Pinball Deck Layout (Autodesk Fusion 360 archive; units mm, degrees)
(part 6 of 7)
sketch "Solenoid Coupling" plane through (0, 0, -32.2) normal (0, 0, 1) x axis (1, 0, 0)
  line L1 (14.8548, -15.2705) -> (9.7533, -24.1063)
  line L2 (30.5284, -24.3335) -> (14.8548, -15.2705)
  line L3 (25.433, -33.159) -> (30.5284, -24.3335)
  line L4 (25.433, -33.159) -> (9.7533, -24.1063)
  line L5 (47.3229, -34.0286) -> (34.864, -26.8366)
  line L6 (30.5284, -24.3335) -> (34.864, -26.8366)
  line L7 (34.864, -26.8366) -> (30.629, -34.173)
  line L8 (13.6506, -26.3564) -> (16.6506, -21.1603)
  line L9 (22.6506, -21.1603) -> (16.6506, -21.1603)
  line L10 (13.6506, -26.3564) -> (16.6506, -21.1603)
  line L11 (51.0602, -47.9614) -> (53.55, -46.5429)
  line L12 (51.0602, -47.9614) -> (42.896, -43.2346)
  line L13 (-25.136, -26.8366) -> (-29.3244, -34.0923)
  line L14 (-45.1452, -15.2705) -> (-50.2467, -24.1063)
  line L15 (-34.567, -33.159) -> (-29.4716, -24.3335)
  line L16 (-46.3494, -26.3564) -> (-43.3494, -21.1603)
  line L17 (-8.2143, -48.5931) -> (-5.4963, -46.9921)
  line L18 (-11.811, -34.5286) -> (-25.136, -26.8366)
  line L19 (-29.4716, -24.3335) -> (-25.136, -26.8366)
  line L20 (-29.4716, -24.3335) -> (-45.1452, -15.2705)
  line L21 (-37.3494, -21.1603) -> (-43.3494, -21.1603)
  line L22 (-46.3494, -26.3564) -> (-43.3494, -21.1603)
  line L23 (-10.945, -35.0285) -> (-11.811, -34.5286)
  line L24 (-15.3719, -42.1478) -> (-16.2379, -41.6478)
  line L25 (-89.4716, -24.3335) -> (-105.1452, -15.2705)
  line L26 (-97.3494, -21.1603) -> (-103.3494, -21.1603)
  line L27 (-67.4648, -48.7967) -> (-64.8096, -47.2494)
  line L28 (-106.3494, -26.3564) -> (-103.3494, -21.1603)
  line L29 (-106.3494, -26.3564) -> (-103.3494, -21.1603)
  line L30 (-69.7504, -35.7181) -> (-70.6165, -35.2181)
  line L31 (-70.6165, -35.2181) -> (-85.136, -26.8366)
  line L32 (-74.5059, -42.6477) -> (-75.3719, -42.1477)
  line L33 (-85.136, -26.8366) -> (-89.3244, -34.0922)
  line L34 (-67.4648, -48.7967) -> (-75.3719, -44.2345)
  line L35 (-89.4716, -24.3335) -> (-85.136, -26.8366)
  line L36 (-94.567, -33.159) -> (-89.4716, -24.3335)
  line L37 (-105.1452, -15.2705) -> (-110.2467, -24.1063)
  line L38 (-94.567, -33.159) -> (-110.2467, -24.1063)
  line L39 (-156.3494, -26.3564) -> (-153.3494, -21.1603)
  line L40 (-155.1452, -15.2705) -> (-160.2467, -24.1063)
  line L41 (-147.3494, -21.1603) -> (-153.3494, -21.1603)
  line L42 (-119.2129, -36.0285) -> (-120.0789, -35.5285)
  line L43 (-116.307, -49.4732) -> (-113.7939, -48.0094)
  line L44 (-156.3494, -26.3564) -> (-153.3494, -21.1603)
  line L45 (-144.567, -33.159) -> (-139.4716, -24.3335)
  line L46 (-134.27, -27.3366) -> (-138.4584, -34.5922)
  line L47 (-144.567, -33.159) -> (-160.2467, -24.1063)
  line L48 (-139.4716, -24.3335) -> (-134.27, -27.3366)
  line L49 (-139.4716, -24.3335) -> (-155.1452, -15.2705)
  line L50 (-120.0789, -35.5285) -> (-134.27, -27.3366)
  line L51 (-123.6398, -43.1477) -> (-124.5059, -42.6477)
  line L52 (-116.307, -49.4732) -> (-124.5058, -44.7345)
  line L53 (-204.567, -33.159) -> (-220.2467, -24.1063)
  line L54 (-182.7738, -43.6477) -> (-183.6398, -43.1477)
  line L55 (-207.3494, -21.1603) -> (-213.3494, -21.1603)
  line L56 (-215.1452, -15.2705) -> (-220.2467, -24.1063)
  line L57 (-216.3494, -26.3564) -> (-213.3494, -21.1603)
  line L58 (-216.3494, -26.3564) -> (-213.3494, -21.1603)
  line L59 (-199.4716, -24.3335) -> (-215.1452, -15.2705)
  line L60 (-199.4716, -24.3335) -> (-193.404, -27.8366)
  line L61 (-178.3469, -36.5285) -> (-179.2129, -36.0285)
  line L62 (-179.2129, -36.0285) -> (-193.404, -27.8366)
  line L63 (-175.4401, -49.9688) -> (-183.6398, -45.2345)
  line L64 (-204.567, -33.159) -> (-199.4716, -24.3335)
  line L65 (-175.4401, -49.9688) -> (-172.9348, -48.5134)
  line L66 (-193.404, -27.8366) -> (-197.5924, -35.0922)
  line L67 (-264.567, -33.159) -> (-280.2467, -24.1063)
  line L68 (-275.1452, -15.2705) -> (-280.2467, -24.1063)
  line L69 (-234.5746, -50.467) -> (-232.0726, -49.0156)
  line L70 (-238.3469, -36.5285) -> (-252.538, -28.3366)
  line L71 (-259.4716, -24.3335) -> (-252.538, -28.3366)
  line L72 (-252.538, -28.3366) -> (-256.7263, -35.5922)
  line L73 (-234.5746, -50.467) -> (-242.7738, -45.7345)
  line L74 (-259.4716, -24.3335) -> (-275.1452, -15.2705)
  line L75 (-267.3494, -21.1603) -> (-273.3494, -21.1603)
  line L76 (-276.3494, -26.3564) -> (-273.3494, -21.1603)
  line L77 (-276.3494, -26.3564) -> (-273.3494, -21.1603)
  line L78 (-264.567, -33.159) -> (-259.4716, -24.3335)
  line L79 (25.433, -33.159) -> (42.896, -43.2346)
  line L80 (30.629, -34.173) -> (29.7699, -35.6612)
  line L81 (-30.2298, -35.6615) -> (-29.3244, -34.0923)
  line L82 (-90.23, -35.6618) -> (-75.3719, -44.2345)
  line L83 (-90.23, -35.6618) -> (-89.3244, -34.0922)
  line L84 (-90.23, -35.6618) -> (-94.567, -33.159)
  line L85 (-144.567, -33.159) -> (-124.5058, -44.7345)
  line L86 (-139.3638, -36.1613) -> (-138.4584, -34.5922)
  line L87 (-204.567, -33.159) -> (-183.6398, -45.2345)
  line L88 (-198.4977, -36.6611) -> (-197.5924, -35.0922)
  line L89 (-264.567, -33.159) -> (-242.7738, -45.7345)
  line L90 (-257.6316, -37.161) -> (-256.7263, -35.5922)
  line L91 (-326.2039, -23.3339) -> (-319.2703, -27.337)
  line L92 (-331.2993, -32.1594) -> (-346.979, -23.1067)
  line L93 (-343.0816, -25.3568) -> (-340.0816, -20.1607)
  line L94 (-299.5746, -50.467) -> (-297.0726, -49.0156)
  line L95 (-343.0816, -25.3568) -> (-340.0816, -20.1607)
  line L96 (-334.0816, -20.1607) -> (-340.0816, -20.1607)
  line L97 (-326.2039, -23.3339) -> (-341.8775, -14.2709)
  line L98 (-303.3473, -36.5287) -> (-319.2703, -27.337)
  line L99 (-331.2993, -32.1594) -> (-326.2039, -23.3339)
  line L100 (-319.2703, -27.337) -> (-323.4586, -34.5926)
  line L101 (-299.5746, -50.467) -> (-307.7738, -45.7345)
  line L102 (-331.2993, -32.1594) -> (-307.7738, -45.7345)
  line L103 (-341.8775, -14.2709) -> (-346.979, -23.1067)
  line L104 (-324.3639, -36.1614) -> (-323.4586, -34.5926)
  line L105 (-326.0961, -35.1618) -> (-324.3639, -36.1614)
  line L106 (-393.0316, -31.1598) -> (-367.7738, -45.7345)
  line L107 (-381.0025, -26.3374) -> (-385.1909, -33.593)
  line L108 (-386.0961, -35.1618) -> (-385.1909, -33.593)
  line L109 (-393.0316, -31.1598) -> (-408.7112, -22.1071)
  line L110 (-403.6098, -13.2713) -> (-408.7112, -22.1071)
  line L111 (-387.9362, -22.3343) -> (-403.6098, -13.2713)
  line L112 (-395.8139, -19.1611) -> (-401.8139, -19.1611)
  line L113 (-387.9362, -22.3343) -> (-381.0025, -26.3374)
  line L114 (-393.0316, -31.1598) -> (-387.9362, -22.3343)
  line L115 (-359.5746, -50.467) -> (-367.7738, -45.7345)
  line L116 (-404.8139, -24.3572) -> (-401.8139, -19.1611)
  line L117 (-363.3476, -36.5288) -> (-381.0025, -26.3374)
  line L118 (-404.8139, -24.3572) -> (-401.8139, -19.1611)
  line L119 (-359.5746, -50.467) -> (-357.0726, -49.0156)
  line L120 (-387.8284, -34.1622) -> (-386.0961, -35.1618)
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  point P3 (16.6506, -21.1603)
  point P13 (16.6506, -21.1603)
  point P16 (13.6506, -26.3564)
  point P22 (-43.3494, -21.1603)
  point P33 (-43.3494, -21.1603)
  point P35 (-46.3494, -26.3564)
  point P48 (-103.3494, -21.1603)
  point P55 (-103.3494, -21.1603)
  point P47 (-106.3494, -26.3564)
  point P67 (-153.3494, -21.1603)
  point P78 (-153.3494, -21.1603)
  point P65 (-156.3494, -26.3564)
  point P92 (-213.3494, -21.1603)
  point P94 (-213.3494, -21.1603)
  point P93 (-216.3494, -26.3564)
  point P111 (-273.3494, -21.1603)
  point P115 (-273.3494, -21.1603)
  point P112 (-276.3494, -26.3564)
  point P127 (29.7699, -35.6612)
  point P130 (-139.3638, -36.1613)
  point P131 (-198.4977, -36.6611)
  point P132 (-257.6316, -37.161)
  point P138 (-340.0816, -20.1607)
  point P139 (-340.0816, -20.1607)
  point P136 (-343.0816, -25.3568)
  point P133 (-324.3639, -36.1614)
  point P155 (-401.8139, -19.1611)
  point P161 (-401.8139, -19.1611)
  point P159 (-404.8139, -24.3572)
  point P158 (-386.0961, -35.1618)
  point P181 (138.3827, -22.1603)
  point P202 (138.3827, -22.1603)
  point P201 (77.5167, -21.6603)
  point P220 (77.5167, -21.6603)
  point P14 (13.6506, -26.3564)
  point P34 (-46.3494, -26.3564)
  point P30 (-11.811, -34.5286)
  point P40 (-10.945, -35.0285)
  point P28 (-16.2379, -41.6478)
  point P41 (-15.3719, -42.1478)
  point P46 (-106.3494, -26.3564)
  point P49 (-69.7504, -35.7181)
  point P61 (-70.6165, -35.2181)
  point P51 (-74.5059, -42.6477)
  point P54 (-75.3719, -42.1477)
  point P74 (-156.3494, -26.3564)
  point P72 (-119.2129, -36.0285)
  point P83 (-120.0789, -35.5285)
  point P75 (-123.6398, -43.1477)
  point P77 (-124.5059, -42.6477)
  point P98 (-216.3494, -26.3564)
  point P91 (-178.3469, -36.5285)
  point P105 (-179.2129, -36.0285)
  point P99 (-182.7738, -43.6477)
  point P101 (-183.6398, -43.1477)
  point P124 (-276.3494, -26.3564)
  point P146 (-343.0816, -25.3568)
  point P153 (-326.0961, -35.1618)
  point P167 (-404.8139, -24.3572)
  point P154 (-387.8284, -34.1622)
  point P203 (135.3827, -27.3564)
  point P208 (74.5167, -26.8564)
  point P210 (109.055, -35.0285)
  point P213 (108.189, -34.5286)
  point P214 (104.6281, -42.1478)
  point P219 (103.7621, -41.6478)
  point P197 (75.7208, -15.7705)
  point P229 (76.5868, -16.2705)
  point P186 (136.5868, -16.2705)
  point P230 (138.3189, -17.2706)
  perpendicular L3 L4
  perpendicular L3 L6
  perpendicular L5 L7
  horizontal L9
  coincident P3 P13
  perpendicular L4 L8
  coincident L8 P16
  coincident L4 P16
  perpendicular L15 L19
  perpendicular L13 L18
  horizontal L21
  coincident P22 P33
  coincident P35 L22
  parallel L18 L23
  perpendicular L36 L38
  perpendicular L35 L36
  perpendicular L31 L33
  horizontal L26
  coincident P48 P55
  perpendicular L28 L38
  coincident P47 L28
  coincident P47 L38
  parallel L30 L31
  perpendicular L45 L47
  perpendicular L45 L48
  perpendicular L46 L50
  horizontal L41
  coincident P67 P78
  perpendicular L39 L47
  coincident P65 L39
  coincident P65 L47
  parallel L42 L50
  perpendicular L53 L64
  perpendicular L60 L64
  perpendicular L62 L66
  horizontal L55
  coincident P92 P94
  perpendicular L53 L57
  coincident P93 L57
  coincident P93 L53
  parallel L61 L62
  perpendicular L67 L78
  perpendicular L71 L78
  perpendicular L70 L72
  horizontal L75
  coincident P111 P115
  perpendicular L67 L77
  coincident P112 L77
  coincident P112 L67
  coincident L79 P127
  parallel L7 L80
  parallel L34 L82
  perpendicular L82 L83
  coincident L85 P130
  perpendicular L85 L86
  coincident L87 P131
  perpendicular L87 L88
  coincident L89 P132
  perpendicular L89 L90
  perpendicular L92 L99
  perpendicular L91 L99
  perpendicular L98 L100
  horizontal L96
  coincident P138 P139
  perpendicular L92 L93
  coincident P136 L93
  coincident P136 L92
  coincident P133 L102
  perpendicular L102 L104
  perpendicular L104 L105
  perpendicular L109 L114
  perpendicular L113 L114
  perpendicular L107 L117
  horizontal L112
  coincident P155 P161
  perpendicular L109 L118
  coincident P159 L118
  coincident P159 L109
  coincident P158 L106
  perpendicular L106 L108
  perpendicular L108 L120
  coincident P181 P202
  coincident P201 P220
  dimension "d206" diameter = 6.5
  dimension "d232" angle L8 L9 = 120
  dimension "d233" distance P13 P14 = 6
  dimension "d237" diameter = 6.5
  dimension "d238" angle L21 L22 = 120
  dimension "d239" distance P33 P34 = 6
  dimension "d240" distance P30 P40 = 1
  dimension "d241" distance P28 P41 = 1
  dimension "d242" diameter = 6.5
  dimension "d243" angle L26 L28 = 120
  dimension "d244" distance P46 P48 = 6
  dimension "d245" distance P49 P61 = 1
  dimension "d246" distance P51 P54 = 1
  dimension "d247" diameter = 6.5
  dimension "d248" angle L39 L41 = 120
  dimension "d249" distance P67 P74 = 6
  dimension "d250" distance P72 P83 = 1
  dimension "d251" distance P75 P77 = 1
  dimension "d252" diameter = 6.5
  dimension "d253" angle L55 L57 = 120
  dimension "d254" distance P94 P98 = 6
  dimension "d255" distance P91 P105 = 1
  dimension "d256" distance P99 P101 = 1
  dimension "d257" diameter = 6.5
  dimension "d258" angle L75 L77 = 120
  dimension "d259" distance P115 P124 = 6
  dimension "d350" radius = 7
  dimension "d351" radius = 7
  dimension "d352" radius = 6.7
  dimension "d353" radius = 7
  dimension "d354" radius = 7
  dimension "d355" radius = 7
  dimension "d421" diameter = 6.5
  dimension "d422" angle L93 L96 = 120
  dimension "d423" distance P139 P146 = 6
  dimension "d424" radius = 7
  dimension "d425" distance P133 P153 = 2
  dimension "d426" diameter = 6.5
  dimension "d427" angle L112 L118 = 120
  dimension "d428" distance P155 P167 = 6
  dimension "d429" radius = 7
  dimension "d430" distance P154 P158 = 2
  dimension "d458" angle = 150
  dimension "d858" diameter = 6.5
  dimension "d859" angle = 120
  dimension "d860" distance P202 P203 = 6
  dimension "d861" diameter = 6.5
  dimension "d862" angle = 120
  dimension "d863" distance P208 P220 = 6
  dimension "d864" distance P210 P213 = 1
  dimension "d865" distance P214 P219 = 1
  dimension "d866" radius = 7
  dimension "d867" radius = 7
  dimension "d868" angle = 150
  dimension "d869" distance P197 P229 = 1
  dimension "d870" distance P186 P230 = 2
work_plane "WorkPlane6" sketch "Flipper" AlongDistance 11
sketch "Rubber Band Line" plane through (0, 0, 11) normal (0, 0, 1) x axis (1, 0, 0)
  line L1 (47.766, 7.9632) -> (0.9915, 12.4623)
  line L2 (0.1878, -12.5003) -> (47.7564, -7.9642)
  line L3 (47.766, 207.9632) -> (0.9915, 212.4623)
  line L4 (0.1878, 187.4997) -> (47.7564, 192.0358)
  arc A1 centre (0, 0) radius 12.5017 clockwise from (0.1878, -12.5003) to (0.9915, 12.4623)
  arc A2 centre (47, 0) radius 8 clockwise from (47.766, 7.9632) to (47.7564, -7.9642)
  arc A3 centre (47, 200) radius 8 clockwise from (47.766, 207.9632) to (47.7564, 192.0358)
  arc A4 centre (0, 200) radius 12.5017 clockwise from (0.1878, 187.4997) to (0.9915, 212.4623)
work_plane "WorkPlane7" PathDistance 0.8475
sketch "Rubber Band profile" plane through (23.6498, 10.2829, 13) normal (0.9954, -0.0957, 0) x axis (0.0957, 0.9954, 0)
  line L1 (-2.5, 5.1) -> (-2.5, -5.1)
  line L2 (2.5, -5.1) -> (2.5, 5.1)
  line L3 (2.5, 7.1) -> (-2.5, 5.1)
  line L4 (2.5, 7.1) -> (2.5, 5.1)
  line L5 (2.5, -7.1) -> (-2.5, -5.1)
  line L6 (2.5, -5.1) -> (2.5, -7.1)
  line L7 (2.5, 207.1) -> (2.5, 205.1)
  line L8 (-2.5, 205.1) -> (-2.5, 194.9)
  line L9 (2.5, 194.9) -> (2.5, 192.9)
  line L10 (2.5, 207.1) -> (-2.5, 205.1)
  line L11 (2.5, 192.9) -> (-2.5, 194.9)
  line L12 (2.5, 194.9) -> (2.5, 205.1)
  circle C1 centre (0, 0) radius 2
  circle C2 centre (0, 200) radius 2
  point P1 (0, 0)
  point P2 (0, 0)
  coincident P1 P2
sweep "Sweep1" sketch "Rubber Band profile" TwistAngle 0 TaperAngle 0
sketch "Silicon Chip Logo Flipper" plane through (0, 0, 25.7) normal (0, 0, 1) x axis (-1, 0, 0)
  line L1 (-47.7564, 7.9642) -> (0, 12.5)
  line L2 (-1.1968, -12.4426) -> (-47.766, -7.9632)
  curve K1
  curve K2
  curve K3
  curve K4
  line L3 (-47.7564, 7.9642) -> (0, 12.5)
  line L4 (-1.1968, -12.4426) -> (-47.766, -7.9632)
  arc A1 centre (0, 0) radius 12.5 clockwise from (0, 12.5) to (-1.1968, -12.4426)
  arc A2 centre (-47, 0) radius 8 clockwise from (-47.766, -7.9632) to (-47.7564, 7.9642)
  arc A3 centre (0, 0) radius 12.5 clockwise from (0, 12.5) to (-1.1968, -12.4426)
  arc A4 centre (-47, 0) radius 8 clockwise from (-47.766, -7.9632) to (-47.7564, 7.9642)
  dimension "d116" Text1-Height = 7
extrude "Extrude31" cut sketch "Flipper Drive Lower Assembly" profile of C2 C3 C4 C5 along normal blind 20
extrude "Extrude28" cut sketch "Silicon Chip Logo Flipper" against normal blind 0.6
sketch "37mm solenoid drill" plane through (0, 0, -46) normal (0, 0, -1) x axis (1, 0, 0)
  line L1 (-72.6464, -35.307) -> (-73.3163, -35.307)
  line L2 (-92.7503, -29.6387) -> (-60.4463, -11.5985)
  line L3 (-82.7298, -46.9948) -> (-92.7503, -29.6387)
  line L4 (-50.4258, -28.9545) -> (-82.7298, -46.9948)
  line L5 (-51.4186, -22.4904) -> (-55.4186, -15.5622)
  line L6 (-49.0676, -21.307) -> (-73.3163, -35.307)
  line L7 (-47.3633, -20.323) -> (-49.0676, -21.307)
  line L8 (-47.3633, -20.323) -> (-53.3977, -23.807)
  line L9 (-60.4463, -11.5985) -> (-53.3977, -23.807)
  line L10 (-39.3006, -23.807) -> (-53.3977, -23.807)
  line L11 (-50.4258, -28.9545) -> (-60.4463, -11.5985)
  line L12 (-92.7503, -29.6387) -> (-60.4463, -11.5985)
  line L13 (-44.7375, -18.807) -> (-49.0676, -21.307)
  circle C1 centre (-77.3163, -28.3788) radius 1.75
  circle C2 centre (-55.9958, -25.307) radius 1.75
  circle C3 centre (-59.9958, -18.3788) radius 1.75
  circle C4 centre (-73.3163, -35.307) radius 1.75
  circle C5 centre (-77.3163, -28.3788) radius 4
  circle C6 centre (-73.3163, -35.307) radius 4
  circle C7 centre (-59.9958, -18.3788) radius 4
  circle C8 centre (-55.9958, -25.307) radius 4
  point P7 (-73.3163, -35.307)
  point P12 (-73.3163, -35.307)
  point P13 (-49.0676, -21.307)
  point P17 (-60.4463, -11.5985)
  point P20 (-92.7503, -29.6387)
  point P25 (-44.7375, -18.807)
  parallel L2 L4
  coincident P7 P12
  perpendicular L5 L6
  horizontal L10
  parallel L9 L11
  parallel L2 L12
  concentric C1 C5
  concentric C4 C6
  concentric C3 C7
  concentric C2 C8
  perpendicular L5 L13
  dimension "d121" diameter C1 = 3.5
  dimension "d122" diameter C2 = 3.5
  dimension "d123" diameter C3 = 3.5
  dimension "d147" diameter C4 = 3.5
  dimension "d329" distance P12 P13 = 28
  dimension "d330" angle L9 L10 = 120
  dimension "d331" distance P17 P20 = 37
  dimension "d332" diameter C5 = 8
  dimension "d333" diameter C6 = 8
  dimension "d334" diameter C7 = 8
  dimension "d335" diameter C8 = 8
  dimension "d370" distance P13 P25 = 5
extrude "Extrude29" cut sketch "37mm solenoid drill" profile of C1 C2 C3 C4 L6 against normal blind 120
move "Move10" RotateAngle 180
sketch "22mm solenoid drill" plane through (0, 0, -45.2) normal (0, 0, -1) x axis (1, 0, 0)
  line L1 (-48.4737, -23.7852) -> (-73.4142, -23.7852)
  line L2 (-27.7707, -26.6775) -> (-54.4238, -26.6775)
  line L3 (-60.8568, -16.5352) -> (-60.4238, -16.2852)
  circle C1 centre (-37.9675, -17.1807) radius 1.8
  circle C2 centre (-56.9579, -14.2884) radius 1.8
  circle C3 centre (-73.4142, -23.7852) radius 1.75
  circle C4 centre (-54.4238, -26.6775) radius 1.75
  circle C5 centre (-54.4238, -26.6775) radius 4
  circle C6 centre (-73.4142, -23.7852) radius 4
  circle C7 centre (-60.4238, -16.2852) radius 1.75
  circle C8 centre (-60.4238, -16.2852) radius 4
  circle C9 centre (-67.4142, -34.1775) radius 1.75
  circle C10 centre (-67.4142, -34.1775) radius 4
  point P4 (-73.4142, -23.7852)
  point P8 (-73.4142, -23.7852)
  point P6 (-54.4238, -26.6775)
  point P10 (-54.4238, -26.6775)
  point P12 (-60.4238, -16.2852)
  point P16 (-60.4238, -16.2852)
  point P17 (-60.8568, -16.5352)
  horizontal L1
  coincident P4 P8
  horizontal L2
  coincident P6 P10
  coincident P12 P16
  dimension "d127" diameter C3 = 3.5
  dimension "d128" diameter C4 = 3.5
  dimension "d339" diameter C5 = 8
  dimension "d340" diameter C6 = 8
  dimension "d469" diameter C7 = 3.5
  dimension "d470" diameter C8 = 8
  dimension "d471" diameter C9 = 3.5
  dimension "d472" diameter C10 = 8
  dimension "d573" distance P16 P17 = 0.5
work_plane "WorkPlane8" sketch "Flipper Drive Perpendicular Plane" AlongDistance 20
sketch "Drive Hole Expansion Calcs" plane through (-11.4715, 16.383, 0) normal (-0.5736, 0.8192, 0) x axis (-0.8192, -0.5736, 0)
  line L1 (-20, -32.2) -> (-18, -32.2)
  line L2 (0, -34.2) -> (20.0402, -34.1996)
  line L3 (20, -30.2) -> (0, -30.2)
  line L4 (0, -34.2) -> (0, -34.2)
  line L5 (0, -30.2) -> (0, -30.2)
  arc A1 centre (20, -32.2) radius 2 clockwise from (20, -30.2) to (19.9599, -34.1996)
  circle C1 centre (10, -32.2) radius 2
  arc A2 centre (0, -32.2) radius 2 clockwise from (0, -34.2) to (0, -30.2)
  point P7 (20.0402, -34.1996)
  point P12 (19.9599, -34.1996)
  point P14 (0, -30.2)
  point P15 (0, -34.2)
  coincident P7 A1
  tangent L2 A2
  tangent L3 A1
  horizontal L4
  parallel L1 L5
  coincident L2 P12
  coincident A2 P14
  coincident A2 P15
  dimension "d171" diameter A2 = 4
  dimension "d172" diameter A1 = 4
  dimension "d174" diameter C1 = 4
extrude "Extrude30" cut sketch "22mm solenoid drill" profile of C3 C4 against normal blind 50
extrude "Extrude33" add sketch "Flipper Drive Top Labelling" profile of C1 C2 along normal blind 1
extrude "Extrude34" add sketch "Flipper Drive Top Labelling" profile of C2 C3 along normal blind 7.7
sketch "Solenoid Drive Washer" plane through (0, 0, -21.4) normal (0, 0, -1) x axis (1, 0, 0)
  line L1 (-20.2309, -4.9709) -> (-24.4204, 2.2855)
  line L2 (-6.7129, -2.3124) -> (-0.123, 7.0989)
  line L3 (6.7129, 2.3124) -> (0.123, -7.0989)
  arc A1 centre (-5, 8.6603) radius 6 clockwise from (-10.8144, 10.1409) to (-6.625, 2.8845)
  circle C1 centre (-5, 8.6603) radius 6
  circle C2 centre (-5, 8.6603) radius 1.75
  arc A2 centre (0, 0) radius 7.1 clockwise from (-0.123, 7.0989) to (6.7129, 2.3124)
  arc A3 centre (0, 0) radius 7.1 clockwise from (0.123, -7.0989) to (-6.7129, -2.3124)
  circle C3 centre (0, 0) radius 15
  circle C4 centre (-5, 208.6603) radius 1.75
  circle C5 centre (-5, 208.6603) radius 6
extrude "Extrude36" new body sketch "Solenoid Drive Washer" profile of A1 C1 C2 blind 1 from offset 0.2 bodies "Drive Arm Washer"
extrude "Extrude37" cut sketch "Flipper Drive Top Labelling" profile of C3 against normal blind 16
extrude "Extrude38" new body sketch "Solenoid Coupling" along normal blind 1.5 and against normal blind 1.5 bodies "Solenoid Coupling 38mm"
extrude "Extrude39" add sketch "Solenoid Coupling" profile of L3 L6 L7 along normal blind 7.6 and against normal blind 7.5
extrude "Extrude40" add sketch "Solenoid Coupling" blind 3 from offset 4.5
extrude "Extrude41" add sketch "Solenoid Coupling" blind -3 from offset -4.5
move "Move17"
move "Move18"
move "Move19"
move_face "MoveFace2"
extrude "Extrude42" new body sketch "Solenoid Coupling" along normal blind 1.5 and against normal blind 1.5 bodies "Solenoid Coupling 41mm", "Solenoid Coupling 42mm", "Solenoid Coupling 40mm", "Solenoid Coupling 43mm", "Solenoid Coupling 39mm"
extrude "Extrude43" new body sketch "Solenoid Coupling" blind 3 from offset 4.5
extrude "Extrude44" new body sketch "Solenoid Coupling" blind -3 from offset -4.5
extrude "Extrude45" add sketch "Solenoid Coupling" profile of L13 L15 L19 L33 L35 L36 L45 L46 L48 L60 L64 L66 L71 L72 L78 along normal blind 5.5 and against normal blind 5.5
chamfer "Chamfer1" distance 2 distance 5
sketch "Coupling base labelling" plane through (0, 0, -31.4) normal (0, 0, 1) x axis (-1, 0, 0)
  dimension "d278" = 6
  dimension "d279" = "'38'"
  dimension "d280" = 6
  dimension "d281" = "'38'"
  dimension "d871" = 6
  dimension "d872" = "'36'"
  dimension "d873" = 6
  dimension "d874" = "'37'"
extrude "Extrude48" add sketch "Flipper Drive" profile of C1 L9 L11 L13 L14 A5 A6 blind 8.8 from offset 11.2
extrude "Extrude49" new body sketch "Flipper Drive" blind 10 from offset 10 bodies "Drive Limiter"
move "Move20"
move "Move21"
extrude "Extrude51" cut sketch "37mm solenoid drill" profile of C1 C2 C3 C4 L6 C5 C6 C7 C8 blind 8 from offset -40
extrude "Extrude52" cut sketch "22mm solenoid drill" profile of C2 C3 C4 C5 C6 C7 C8 C9 C10 blind 8 from offset -39
extrude "Extrude53" cut sketch "22mm solenoid drill" profile of C2 C3 C4 C7 C9 against normal blind 100 taper 0.1
extrude "Extrude46" cut sketch "Coupling base labelling" against normal blind 0.4
sketch "Coupling Labelling" plane through (0, 0, -30.7) normal (0, 0, 1) x axis (-1, 0, 0)
  dimension "d284" = 6
  dimension "d285" = "'39'"
  dimension "d286" = 6
  dimension "d287" = 0 (= "Text2-Text")
  dimension "d288" = 6
  dimension "d289" = "'39'"
  dimension "d290" = 6
  dimension "d291" = "'41'"
  dimension "d292" = 6
  dimension "d293" = "'42'"
  dimension "d294" = 6
  dimension "d295" = "'43'"
extrude "Extrude47" cut sketch "Coupling Labelling" against normal blind 0.4
work_plane "WorkPlane10" AlongDistance 2.7
move "Move22"
move "Move23"
extrude "Extrude54" cut sketch "Flipper" profile of C2 C3 blind -12 from offset -20
move_face "MoveFace3"
sketch "Flipper Dimensions" plane through (0, 0, 0) normal (0, 0, -1) x axis (1, 0, 0)
  dimension "d371" = 6
  dimension "d377" = 6
  dimension "d378" = "'Flipper + 1'"
  dimension "d379" = 6
  dimension "d380" = "'Flipper+0.5'"
extrude "Extrude57" cut sketch "Flipper Dimensions" against normal blind 0.4
move_face "MoveFace4"
move_face "MoveFace5"
move "Move26"
sketch "Flipper Labelling + 1" plane through (0, 0, 0.7) normal (0, 0, 1) x axis (1, 0, 0)
  curve K1
  curve K2
  curve K3
  curve K4
  line L1 (47.766, 7.9632) -> (1.1968, 12.4426)
  line L2 (0, -12.5) -> (47.7564, -7.9642)
  line L3 (47.766, 7.9632) -> (1.1968, 12.4426)
  line L4 (0, -12.5) -> (47.7564, -7.9642)
  line L5 (47.766, 7.9632) -> (1.1968, 12.4426)
  line L6 (0, -12.5) -> (47.7564, -7.9642)
  circle C1 centre (0, 0) radius 6.8
  arc A1 centre (0, 0) radius 12.5 clockwise from (0, -12.5) to (1.1968, 12.4426)
  arc A2 centre (47, 0) radius 8 clockwise from (47.766, 7.9632) to (47.7564, -7.9642)
  circle C2 centre (0, 0) radius 6.8
  arc A3 centre (0, 0) radius 12.5 clockwise from (0, -12.5) to (1.1968, 12.4426)
  arc A4 centre (47, 0) radius 8 clockwise from (47.766, 7.9632) to (47.7564, -7.9642)
  circle C3 centre (0, 0) radius 6.8
  arc A5 centre (0, 0) radius 12.5 clockwise from (0, -12.5) to (1.1968, 12.4426)
  arc A6 centre (47, 0) radius 8 clockwise from (47.766, 7.9632) to (47.7564, -7.9642)
  dimension "d397" Text1-Height = 7
  dimension "d398" Flipper+1 = "'Flipper+1'"
extrude "Extrude64" new body sketch "Bushing" profile of C1 C2 blind -9.8 from offset -0.6 bodies "Bushing + 1"
sketch "Sketch35" plane through (0, 0, 0) normal (0, 1, 0) x axis (1, 0, 0)
  dimension "d412" = 3
  dimension "d413" = "'Bushing+1'"
emboss "Emboss1" sketch "Sketch35" Depth -0.4 Horizontal Distance 0 Vertical Distance 0 Rotation Angle 0
extrude "Extrude65" new body sketch "Washers Upper" profile of C1 C2 blind -0.6 from offset -0.1 bodies "Washer 0.6"
extrude "Extrude66" new body sketch "Solenoid Coupling" along normal blind 1.5 and against normal blind 1.5 bodies "Solenoid Coupling 47mm", "Solenoid Coupling 45mm"
chamfer "Chamfer2" distance 2 distance 4
extrude "Extrude67" add sketch "Solenoid Coupling" profile of L91 L99 L100 L102 L104 L105 L106 L107 L108 L113 L114 L120 along normal blind 5.5 and against normal blind 5.5
extrude "Extrude68" add sketch "Solenoid Coupling" blind -3 from offset -4.5
extrude "Extrude69" add sketch "Solenoid Coupling" blind 3 from offset 4.5
chamfer "Chamfer3" distance 4 distance 2
chamfer "Chamfer4" distance 4 distance 2
sketch "Sketch36" plane through (0, 0, -33.7) normal (0, 0, -1) x axis (1, 0, 0)
  dimension "d451" = 6
  dimension "d452" = "'45'"
  dimension "d453" = 6
  dimension "d454" = "'47'"
extrude "Extrude70" cut sketch "Sketch36" against normal blind 0.4
move "Move27"
sketch "Filpper-Straight" plane through (0, 0, 0) normal (0, 0, 1) x axis (1, 0, 0)
  line L1 (-5.745, 3.7993) -> (5.745, 3.7993)
  line L2 (47.7564, -7.9642) -> (0, -12.5)
  line L3 (-5.745, -3.7993) -> (5.745, -3.7993)
  line L4 (47.766, 7.9632) -> (1.1968, 12.4426)
  line L5 (47.766, 207.9632) -> (1.1968, 212.4426)
  line L6 (-5.745, 196.2007) -> (5.745, 196.2007)
  line L7 (47.7564, 192.0358) -> (0, 187.5)
  line L8 (-5.745, 203.7993) -> (5.745, 203.7993)
  arc A1 centre (47, 0) radius 8 clockwise from (47.766, 7.9632) to (47.7564, -7.9642)
  circle C1 centre (4.3, 0) radius 1.4
  circle C2 centre (0, 0) radius 6.8
  arc A2 centre (0, 0) radius 12.5 clockwise from (2.3532, -12.2765) to (1.1968, 12.4426)
  circle C3 centre (-4.3, 0) radius 1.4
  circle C4 centre (0, 200) radius 6.8
  arc A3 centre (0, 200) radius 12.5 clockwise from (2.3532, 187.7235) to (1.1968, 212.4426)
  circle C5 centre (-4.3, 200) radius 1.4
  arc A4 centre (47, 200) radius 8 clockwise from (47.766, 207.9632) to (47.7564, 192.0358)
  circle C6 centre (4.3, 200) radius 1.4
  point P7 (0, 0)
  point P8 (0, 0)
  point P10 (0, -12.5)
  point P12 (2.3532, -12.2765)
  point P13 (0, 0)
  point P19 (0, 200)
  point P29 (0, 200)
  point P17 (0, 187.5)
  point P28 (2.3532, 187.7235)
  point P21 (0, 200)
  coincident P7 P8
  coincident P10 A2
  tangent A1 L2
  tangent A2 L4
  tangent A1 L4
  coincident P12 L2
  coincident P7 P13
  coincident P19 P29
  coincident P17 A3
  tangent A4 L7
  tangent A3 L5
  tangent L5 A4
  coincident P28 L7
  coincident P21 P29
  dimension "d473" diameter C2 = 13.6
  dimension "d474" diameter C1 = 2.8
  dimension "d475" diameter C3 = 2.8
  dimension "d606" diameter C4 = 13.6
  dimension "d607" diameter C6 = 2.8
  dimension "d608" diameter C5 = 2.8
extrude "Extrude71" new body sketch "Filpper-Straight" profile of C1 C2 L1 C3 L3 blind -31.6 from offset 0.4 bodies "Flipper_Straight"
extrude "Extrude72" cut sketch "Filpper-Straight" profile of C2 L1 L3 blind -19 taper 3 from offset -22.3
extrude "Extrude73" add sketch "Filpper-Straight" profile of A1 C1 C2 A2 L1 C3 L2 L3 L4 blind 25 from offset 0.4
sweep "Sweep3" sketch "Rubber Band profile" TwistAngle 0 TaperAngle 0
extrude "Extrude74" cut sketch "Filpper-Straight" profile of C1 C3 blind -11 from offset -21
extrude "Extrude75" cut sketch "Silicon Chip Logo Flipper" against normal blind 0.4
extrude "Extrude76" new body sketch "Filpper-Straight" profile of A1 C1 C2 A2 L1 C3 L2 L3 L4 blind 25 from offset 0.4 bodies "Flipper Straight + 1"
sweep "Sweep4" sketch "Rubber Band profile" TwistAngle 0 TaperAngle 0
extrude "Extrude77" add sketch "Filpper-Straight" profile of C1 C2 L1 C3 L3 blind -32.6 from offset 0.4
extrude "Extrude78" cut sketch "Filpper-Straight" profile of C2 L1 L3 blind -19 taper 3 from offset -23.3
extrude "Extrude79" cut sketch "Filpper-Straight" profile of C1 C3 blind -19 from offset -22
extrude "Extrude80" cut sketch "Silicon Chip Logo Flipper" against normal blind 0.4
combine "Combine2" bodies "Bushing + 1"
sketch "Sketch38" plane through (0, 0, -31.2) normal (0, 0, -1) x axis (1, 0, 0)
  line L1 (3.473, -19.6962) -> (2.6047, -14.7721)
  line L2 (9.6418, -11.4907) -> (12.8558, -15.3209)
  line L3 (-3.473, 19.6962) -> (-2.6047, 14.7721)
  line L4 (-9.6418, 11.4907) -> (-12.8558, 15.3209)
  line L5 (0.4316, 7.0869) -> (-6.5119, -2.8294)
  line L6 (-0.4316, -7.0869) -> (6.5119, 2.8294)
  line L7 (13.209, 4.0188) -> (9.5966, 1.4894)
  line L8 (13.5885, 3.4768) -> (13.209, 4.0188)
  line L9 (9.9761, 0.9473) -> (13.5885, 3.4768)
  line L10 (10.9209, -0.4021) -> (9.9761, 0.9473)
  line L11 (10.4376, -0.7405) -> (10.9209, -0.4021)
  line L12 (8.1644, 2.5059) -> (10.4376, -0.7405)
  line L13 (8.6478, 2.8444) -> (8.1644, 2.5059)
  line L14 (9.5966, 1.4894) -> (8.6478, 2.8444)
  curve K1 (10.9221, 5.2155) -> (11.2016, 6.4396)
  curve K2 (10.0639, 4.2648) -> (10.9221, 5.2155)
  curve K3 (8.0838, 3.6944) -> (10.0639, 4.2648)
  curve K4 (6.517, 4.7041) -> (8.0838, 3.6944)
  curve K5 (6.072, 5.9164) -> (6.517, 4.7041)
  curve K6 (6.3416, 7.1398) -> (6.072, 5.9164)
  curve K7 (7.2737, 8.1485) -> (6.3416, 7.1398)
  curve K8 (8.5645, 8.6776) -> (7.2737, 8.1485)
  curve K9 (9.8079, 8.4865) -> (8.5645, 8.6776)
  curve K10 (10.7572, 7.669) -> (9.8079, 8.4865)
  curve K11 (11.2016, 6.4396) -> (10.7572, 7.669)
  line L15 (-9.5357, -4.182) -> (-11.6277, -5.6469)
  line L16 (-9.3162, -4.4955) -> (-9.5357, -4.182)
  line L17 (-11.7736, -6.2162) -> (-9.3162, -4.4955)
  line L18 (-12.1164, -5.7268) -> (-11.7736, -6.2162)
  line L19 (-10.7837, -3.9267) -> (-12.1164, -5.7268)
  curve K12 (-10.5021, -3.5547) -> (-10.7837, -3.9267)
  curve K13 (-10.9876, -3.6998) -> (-10.5021, -3.5547)
  line L20 (-13.1094, -4.3086) -> (-10.9876, -3.6998)
  line L21 (-13.4157, -3.8711) -> (-13.1094, -4.3086)
  line L22 (-10.9583, -2.1504) -> (-13.4157, -3.8711)
  line L23 (-10.7388, -2.4638) -> (-10.9583, -2.1504)
  line L24 (-12.7956, -3.904) -> (-10.7388, -2.4638)
  line L25 (-10.2388, -3.1779) -> (-12.7956, -3.904)
  line L26 (-10.0334, -3.4713) -> (-10.2388, -3.1779)
  line L27 (-11.6277, -5.6469) -> (-10.0334, -3.4713)
  line L28 (-9.7284, -5.9583) -> (-9.2708, -5.6378)
  line L29 (-9.2225, -6.6808) -> (-9.7284, -5.9583)
  line L30 (-9.5108, -6.8827) -> (-9.2225, -6.6808)
  line L31 (-10.2414, -5.8428) -> (-9.5108, -6.8827)
  line L32 (-9.3295, -5.2043) -> (-10.2414, -5.8428)
  curve K14 (-8.6958, -5.4975) -> (-9.3295, -5.2043)
  curve K15 (-8.2332, -5.953) -> (-8.6958, -5.4975)
  curve K16 (-7.9275, -6.7196) -> (-8.2332, -5.953)
  curve K17 (-8.0631, -7.4803) -> (-7.9275, -6.7196)
  curve K18 (-8.6129, -8.0901) -> (-8.0631, -7.4803)
  curve K19 (-9.3876, -8.409) -> (-8.6129, -8.0901)
  curve K20 (-10.1517, -8.3007) -> (-9.3876, -8.409)
  curve K21 (-10.7568, -7.7576) -> (-10.1517, -8.3007)
  curve K22 (-11.0079, -7.2152) -> (-10.7568, -7.7576)
  curve K23 (-11.0039, -6.709) -> (-11.0079, -7.2152)
  curve K24 (-10.7319, -6.2412) -> (-11.0039, -6.709)
  line L33 (-10.446, -6.4783) -> (-10.7319, -6.2412)
  curve K25 (-10.6448, -6.8223) -> (-10.446, -6.4783)
  curve K26 (-10.6523, -7.1773) -> (-10.6448, -6.8223)
  curve K27 (-10.4797, -7.5611) -> (-10.6523, -7.1773)
  curve K28 (-10.1419, -7.8991) -> (-10.4797, -7.5611)
  curve K29 (-9.7797, -8.0364) -> (-10.1419, -7.8991)
  curve K30 (-9.428, -8.0213) -> (-9.7797, -8.0364)
  curve K31 (-8.8678, -7.7689) -> (-9.428, -8.0213)
  curve K32 (-8.3972, -7.2708) -> (-8.8678, -7.7689)
  curve K33 (-8.2993, -6.7113) -> (-8.3972, -7.2708)
  curve K34 (-8.5136, -6.1769) -> (-8.2993, -6.7113)
  curve K35 (-8.8836, -5.8215) -> (-8.5136, -6.1769)
  curve K36 (-9.2708, -5.6378) -> (-8.8836, -5.8215)
  line L34 (-6.6506, -8.3024) -> (-8.818, -9.8201)
  line L35 (-6.4229, -8.6276) -> (-6.6506, -8.3024)
  line L36 (-8.5903, -10.1453) -> (-6.4229, -8.6276)
  line L37 (-8.0234, -10.9549) -> (-8.5903, -10.1453)
  line L38 (-8.3134, -11.158) -> (-8.0234, -10.9549)
  line L39 (-9.6773, -9.2101) -> (-8.3134, -11.158)
  line L40 (-9.3873, -9.0071) -> (-9.6773, -9.2101)
  line L41 (-8.818, -9.8201) -> (-9.3873, -9.0071)
  line L42 (8.4474, 10.819) -> (6.7823, 9.6531)
  line L43 (8.827, 10.277) -> (8.4474, 10.819)
  line L44 (4.7312, 7.4091) -> (8.827, 10.277)
  line L45 (3.6494, 8.9541) -> (4.7312, 7.4091)
  curve K37 (3.2522, 9.6045) -> (3.6494, 8.9541)
  curve K38 (3.0895, 10.2442) -> (3.2522, 9.6045)
  curve K39 (3.255, 10.8493) -> (3.0895, 10.2442)
  curve K40 (3.7267, 11.3649) -> (3.255, 10.8493)
  curve K41 (4.8438, 11.6516) -> (3.7267, 11.3649)
  curve K42 (6.0468, 10.7035) -> (4.8438, 11.6516)
  line L46 (6.7823, 9.6531) -> (6.0468, 10.7035)
  arc A1 centre (0, 0) radius 20 clockwise from (12.8558, -15.3209) to (3.473, -19.6962)
  arc A2 centre (0, 0) radius 15 clockwise from (-2.6047, 14.7721) to (9.6418, -11.4907)
  arc A3 centre (0, 0) radius 20 clockwise from (-12.8558, 15.3209) to (-3.473, 19.6962)
  arc A4 centre (0, 0) radius 15 clockwise from (2.6047, -14.7721) to (-9.6418, 11.4907)
  circle C1 centre (-5, 8.6603) radius 5
  arc A5 centre (0, 0) radius 7.1 clockwise from (-0.4316, -7.0869) to (-6.5119, -2.8294)
  arc A6 centre (0, 0) radius 7.1 clockwise from (0.4316, 7.0869) to (6.5119, 2.8294)
combine "Combine1" bodies "Bushing + 1"
extrude "Extrude81" cut sketch "Flipper Drive" profile of C2 C4 C6 C8 along normal blind 20
extrude "Extrude82" cut sketch "Flipper Drive" profile of C2 C4 C6 C8 along normal blind 20
extrude "Extrude85" add sketch "Flipper Drive" profile of L20 L23 L24 L26 A12 A13 C3 C5 A21 blind 3.5 from offset 10
mirror "Mirror6" mirrorStitchTolerance 0.1 bodies "Drive Limiter Mirrored"
extrude "Extrude86" cut sketch "Flipper Drive" profile of L5 L7 L15 L17 L20 L23 L24 L26 A14 A15 A16 C2 C3 C4 C5 C6 C7 C8 C9 along normal blind 3.8
mirror "Mirror7" mirrorStitchTolerance 0.1 bodies "Base and Bushing 9mm deck Mirrored"
extrude "Extrude83" cut sketch "Flipper Drive" profile of L5 L7 L15 L17 L20 L23 L24 L26 A14 A15 A16 C2 C3 C4 C5 C6 C7 C8 C9 along normal blind 3.8
extrude "Extrude84" add sketch "Flipper Drive" profile of L20 L23 L24 L26 A12 A13 C3 C5 A21 blind 3.5 from offset 10
extrude "Extrude87" cut sketch "Flipper Drive Top Labelling" profile of C2 C3 blind 4 from offset -7.8
mirror "Mirror8" mirrorStitchTolerance 0.1 bodies "Flipper Drive Mirrored"
fillet "Fillet6" radius 2
fillet "Fillet7" radius 2
fillet "Fillet8" radius 2
copy_paste_bodies "CopyPasteBodies6"
mirror "Mirror9" mirrorStitchTolerance 0.1 bodies "Base and Bushing 12mm deck Mirrored"
extrude "Extrude88" add of existing geometry blind 3
extrude "Extrude89" add of existing geometry blind 3
extrude "Extrude90" new body sketch "Flipper" + "Filpper-Straight" profile of S1:A1 S1:A2 S1:L1 S1:L2 S1:C1 S1:L4 S1:L3 S1:C2 S1:C3 S2:A1 S2:C1 S2:C2 S2:A2 S2:L1 S2:C3 S2:L2 S2:L3 S2:L4 blind 25 bodies "Flipper + 2"
extrude "Extrude91" add sketch "Filpper-Straight" profile of C1 C2 L1 C3 L3 against normal blind 33.2
extrude "Extrude92" cut sketch "Filpper-Straight" profile of C2 L1 L3 blind -20 taper 3 from offset -24.3
extrude "Extrude93" cut sketch "Filpper-Straight" profile of C1 C3 blind -15 from offset -23
sweep "Sweep5" sketch "Rubber Band profile" TwistAngle 0 TaperAngle 0
fillet "Fillet9" radius 2
extrude "Extrude94" new body sketch "Filpper-Straight" profile of A1 C1 C2 A2 L1 C3 L2 L3 L4 along normal blind 25 bodies "Flipper + 3"
extrude "Extrude95" add sketch "Filpper-Straight" profile of C1 C2 L1 C3 L3 against normal blind 34.2
extrude "Extrude96" cut sketch "Filpper-Straight" profile of C2 L1 L3 blind -20 taper 3 from offset -25.3 (= "0.0 mm - 25.30 mm")
extrude "Extrude97" cut sketch "Filpper-Straight" profile of C1 C3 blind -20 from offset -25.3
sweep "Sweep6" sketch "Rubber Band profile" TwistAngle 0 TaperAngle 0
fillet "Fillet10" radius 2
extrude "Extrude98" new body sketch "Filpper-Straight" profile of A1 C1 C2 A2 L1 C3 L2 L3 L4 along normal blind 25 bodies "Flipper + 4"
extrude "Extrude99" add sketch "Filpper-Straight" profile of C1 C2 L1 C3 L3 against normal blind 35.2
extrude "Extrude100" cut sketch "Filpper-Straight" profile of C2 L1 L3 blind -20 taper 3 from offset -26.3
extrude "Extrude101" cut sketch "Filpper-Straight" profile of C1 C3 blind -20 from offset -26
sweep "Sweep7" sketch "Rubber Band profile" TwistAngle 0 TaperAngle 0
fillet "Fillet11" radius 2
sketch "Sketch39" plane through (0, 0, -0.4) normal (0, 0, -1) x axis (1, 0, 0)
  circle C1 centre (0, 0) radius 7.3
  circle C2 centre (0, 0) radius 13.5
extrude "Extrude102" new body sketch "Bushing" profile of C1 C2 blind -9.6 from offset -0.6 bodies "Double Drive 9mm deck"
sketch "Double Drive Flipper" plane through (0, 0, -10.2) normal (0, 0, -1) x axis (1, 0, 0)
  line L1 (80, 27) -> (-80, 27)
  line L2 (80, -27) -> (80, 27)
  line L3 (-80, -27) -> (80, -27)
  line L4 (-80, 27) -> (-80, -27)
  circle C1 centre (0, 0) radius 7.3
  circle C2 centre (-74, 21) radius 2.25
  circle C3 centre (-74, 21) radius 4
  circle C4 centre (-44, -21) radius 2.25
  circle C5 centre (-44, -21) radius 4
  circle C6 centre (74, -21) radius 2.25
  circle C7 centre (74, -21) radius 4
  circle C8 centre (44, 21) radius 4
  circle C9 centre (44, 21) radius 2.25
  circle C10 centre (-56.5, -14.5) radius 1.8
  circle C11 centre (-71.5, -2.5) radius 1.8
  circle C12 centre (56.5, 14.5) radius 1.8
  circle C13 centre (71.5, 2.5) radius 1.8
  circle C14 centre (-71.5, -2.5) radius 4
  circle C15 centre (-56.5, -14.5) radius 4
  circle C16 centre (56.5, 14.5) radius 4
  circle C17 centre (71.5, 2.5) radius 4
  point P1 (0, 0)
  point P6 (0, 0)
  horizontal L1
  perpendicular L1 L2
  perpendicular L2 L3
  perpendicular L1 L4
  coincident P1 P6
  concentric C2 C3
  concentric C4 C5
  concentric C8 C9
  concentric C6 C7
  concentric C11 C14
  concentric C10 C15
  concentric C12 C16
  concentric C13 C17
  dimension "d739" diameter C2 = 4.5
  dimension "d740" diameter C3 = 8
  dimension "d741" diameter C4 = 4.5
  dimension "d742" diameter C5 = 8
  dimension "d743" diameter C9 = 4.5
  dimension "d744" diameter C8 = 8
  dimension "d745" diameter C6 = 4.5
  dimension "d746" diameter C7 = 8
  dimension "d749" diameter C14 = 8
  dimension "d750" diameter C15 = 8
  dimension "d751" diameter C16 = 8
  dimension "d752" diameter C17 = 8
extrude "Extrude103" add sketch "Double Drive Flipper" profile of L1 L2 L3 L4 C1 along normal blind 10
extrude "Extrude104" new body sketch "Flipper Drive" blind 8.8 from offset 12.2 bodies "Flipper Drive Double"
extrude "Extrude105" add sketch "Flipper Drive Top Labelling" profile of C1 C2 C3 C6 C7 C8 blind 1 from offset 1
extrude "Extrude106" add sketch "Flipper Drive Top Labelling" profile of C2 C3 C6 C7 blind 3.4 from offset 2
extrude "Extrude107" cut sketch "Flipper Drive Top Labelling" profile of C3 C6 along normal blind 10 and against normal blind 10
extrude "Extrude108" cut sketch "Flipper Drive Top Labelling" profile of C2 C3 C6 C7 blind -5 from offset -3.8
extrude "Extrude110" cut sketch "Flipper Drive" profile of A2 L1 L2 L3 A3 A4 L5 L7 L9 L11 L13 L14 L15 L17 L18 L20 L21 L23 L24 L26 blind 8.8 from offset 12.2
extrude "Extrude111" add sketch "Flipper Drive" profile of A2 L1 L2 L3 A3 A4 L5 L7 L9 L11 L13 L14 L15 L17 L63 L64 L65 L66 blind 8.8 taper 3 from offset 12.2
extrude "Extrude112" cut sketch "Flipper Drive Top Labelling" profile of C2 C3 C6 C7 blind -4 from offset -3.8
sketch "Solenoid Coupling Double 41mm" plane through (0, 0, -32.2) normal (0, 0, -1) x axis (1, 0, 0)
  line L1 (40.1052, 4.4601) -> (40.1053, 14.6628)
  line L2 (22, 4.472) -> (16.9937, 4.472)
  line L3 (16.9926, 14.6618) -> (22, 14.6628)
  line L4 (22, 14.6628) -> (40.1053, 14.6628)
  line L5 (22, 14.6628) -> (22, 4.472)
  line L6 (22, 4.472) -> (40.1052, 4.4601)
  line L7 (-9.2901, 14.6544) -> (-0.1612, 14.657)
  line L8 (-9.2901, 14.6544) -> (-10.8159, 11.9867)
  line L9 (16.9926, 14.6618) -> (16.9931, 12.8497)
  line L10 (16.9937, 4.472) -> (16.9931, 12.8497)
  line L11 (0.2287, 4.4708) -> (16.9937, 4.472)
  line L12 (16.9926, 14.6618) -> (-0.1612, 14.657)
  line L13 (-16.9926, -14.6618) -> (-22, -14.6628)
  line L14 (9.2901, -14.6544) -> (10.8159, -11.9867)
  line L15 (-40.1052, -4.4601) -> (-40.1053, -14.6628)
  line L16 (-16.9937, -4.472) -> (-16.9931, -12.8497)
  line L17 (-22, -4.472) -> (-40.1052, -4.4601)
  line L18 (-16.9926, -14.6618) -> (-16.9931, -12.8497)
  line L19 (-22, -14.6628) -> (-40.1053, -14.6628)
  line L20 (-22, -4.472) -> (-16.9937, -4.472)
  line L21 (-16.9926, -14.6618) -> (0.1612, -14.657)
  line L22 (9.2901, -14.6544) -> (0.1612, -14.657)
  line L23 (-0.2287, -4.4708) -> (-16.9937, -4.472)
  line L24 (-22, -14.6628) -> (-22, -4.472)
  arc A1 centre (-5, 8.6603) radius 6.7 clockwise from (0.2287, 4.4708) to (-10.8159, 11.9867)
  circle C1 centre (35.6066, 8.6557) radius 1.9
  circle C2 centre (-5, 8.6603) radius 3.25
  circle C3 centre (5, -8.6603) radius 3
  circle C4 centre (-35.6066, -8.6557) radius 1.9
  arc A2 centre (5, -8.6603) radius 6.7 clockwise from (-0.2287, -4.4708) to (10.8159, -11.9867)
  circle C5 centre (5, -8.6603) radius 3.25
extrude "Extrude113" new body sketch "Solenoid Coupling Double 41mm" profile of L7 L8 L9 A1 C2 L10 L11 L12 blind 3 from offset 0.1 bodies "Solenoid Coupling Double 41mm"
extrude "Extrude114" add sketch "Solenoid Coupling Double 41mm" profile of L2 L3 L5 L9 L10 along normal blind 7.5 and against normal blind 7.5
extrude "Extrude115" add sketch "Solenoid Coupling Double 41mm" profile of L1 L4 L5 L6 C1 blind 3 from offset 4.5
extrude "Extrude116" add sketch "Solenoid Coupling Double 41mm" profile of L1 L4 L5 L6 C1 blind -3 from offset -4.5
fillet "Fillet12" radius 4
sketch "Solenoid 22mm double" plane through (0, 0, -20.2) normal (0, 0, -1) x axis (1, 0, 0)
  line L1 (80, -27) -> (-80, -27)
  line L2 (80, 27) -> (80, -27)
  line L3 (-80, 27) -> (80, 27)
  line L4 (-80, -27) -> (-80, 27)
  line L5 (51.5, 19.5) -> (51.5, -2.5)
  line L6 (77.5, 19.5) -> (51.5, 19.5)
  line L7 (51.5, -2.5) -> (77.5, -2.5)
  line L8 (77.5, -2.5) -> (77.5, 19.5)
  line L9 (-51.5, -19.5) -> (-51.5, 2.5)
  line L10 (-77.5, -19.5) -> (-51.5, -19.5)
  line L11 (-77.5, 2.5) -> (-77.5, -19.5)
  line L12 (-51.5, 2.5) -> (-77.5, 2.5)
  circle C1 centre (0, 0) radius 7.3
  circle C2 centre (71.5, 2.5) radius 1.8
  circle C3 centre (56.5, 14.5) radius 1.8
  circle C4 centre (-56.5, -14.5) radius 1.8
  circle C5 centre (-71.5, -2.5) radius 1.8
  point P7 (77.5, 19.5)
  point P14 (77.5, 19.5)
  point P10 (77.5, 19.5)
  point P16 (-77.5, -19.5)
  point P24 (-77.5, -19.5)
  point P19 (-77.5, -19.5)
  coincident P7 P14
  perpendicular L7 L8
  perpendicular L5 L7
  coincident P7 P10
  perpendicular L6 L8
  coincident P16 P24
  perpendicular L11 L12
  perpendicular L9 L12
  coincident P19 P24
  perpendicular L10 L11
extrude "Extrude117" new body sketch "Solenoid 22mm double" profile of L5 C2 L6 C3 L7 L8 along normal blind 25 bodies "Solenoid 22mm Double"
sketch "Solenoid 22mm Plunger double" plane through (51.5, 0, 0) normal (-1, 0, 0) x axis (0, -1, 0)
  line L1 (-2.5, -20.2) -> (19.5, -20.2)
  line L2 (-2.5, -45.2) -> (-2.5, -20.2)
  line L3 (19.5, -45.2) -> (-2.5, -45.2)
  line L4 (19.5, -20.2) -> (19.5, -45.2)
  line L5 (19.5, -45.2) -> (-2.5, -20.2)
  line L6 (8.5, -32.7) -> (19.5, -20.2)
  circle C1 centre (8.5, -32.7) radius 4.25
  point P3 (-2.5, -20.2)
  point P7 (-2.5, -20.2)
  point P5 (19.5, -45.2)
  point P8 (19.5, -45.2)
  point P2 (19.5, -20.2)
  point P9 (19.5, -20.2)
  point P10 (8.5, -32.7)
  coincident P3 P7
  coincident P5 P8
  coincident P2 P9
  midpoint L5 P10
  dimension "d722" diameter C1 = 8.5
extrude "Extrude118" add sketch "Solenoid 22mm Plunger double" profile of C1 along normal blind 20
extrude "Extrude119" new body sketch "Solenoid 22mm double" profile of L9 L10 C4 C5 L11 L12 along normal blind 25 bodies "Solenoid 22mm Double 2"
sketch "Solenoid 22mm Plunger Double 2" plane through (-51.5, 0, 0) normal (1, 0, 0) x axis (0, 1, 0)
  line L1 (-2.5, -20.2) -> (19.5, -20.2)
  line L2 (-2.5, -45.2) -> (-2.5, -20.2)
  line L3 (19.5, -45.2) -> (-2.5, -45.2)
  line L4 (19.5, -20.2) -> (19.5, -45.2)
  circle C1 centre (8.6603, -32.2) radius 4.25
  point P6 (8.6603, -32.2)
  point P7 (8.6603, -32.2)
  coincident P6 P7
  dimension "d727" diameter C1 = 8.5
extrude "Extrude120" add sketch "Solenoid 22mm Plunger Double 2" profile of C1 along normal blind 20
extrude "Extrude121" new body sketch "Flipper Drive" blind 10 from offset 11 bodies "Drive Limiter Double"
extrude "Extrude122" add sketch "Flipper Drive" blind 3.5 from offset 11
extrude "Extrude123" cut sketch "Double Drive Flipper" profile of C2 C4 C6 C9 along normal blind 20
extrude "Extrude124" cut sketch "Solenoid 22mm double" profile of C2 C3 C4 C5 against normal blind 20
extrude "Extrude125" cut sketch "Double Drive Flipper" profile of C10 C11 C12 C13 C14 C15 C16 C17 along normal blind 6
extrude "Extrude126" cut sketch "Flipper Drive" profile of L5 L7 L15 L17 L20 L23 L24 L26 A14 A15 A16 C2 C3 C4 C5 C6 C7 C8 C9 along normal blind 5
extrude "Extrude127" cut sketch "Flipper Drive" profile of C2 C4 C6 C8 along normal blind 12
mirror "Mirror10" mirrorStitchTolerance 0.1 bodies "Flipper Drive Double Mirrored"
sketch "Flipper 90" plane through (0, 0, 0) normal (0, 0, 1) x axis (1, 0, 0)
  line L1 (3.7993, 5.745) -> (3.7993, -5.745)
  line L2 (-3.7993, 5.745) -> (-3.7993, -5.745)
  line L3 (47.766, 7.9632) -> (1.1968, 12.4426)
  line L4 (47.7564, -7.9642) -> (0, -12.5)
  arc A1 centre (0, 0) radius 12.5 clockwise from (2.3532, -12.2765) to (1.1968, 12.4426)
  circle C1 centre (0, 4.3) radius 1.4
  arc A2 centre (47, 0) radius 8 clockwise from (47.766, 7.9632) to (47.7564, -7.9642)
  circle C2 centre (0, 0) radius 6.8
  circle C3 centre (0, -4.3) radius 1.4
  point P6 (0, 0)
  point P7 (0, 0)
  point P9 (0, -12.5)
  point P11 (2.3532, -12.2765)
  point P12 (0, 0)
  coincident P6 P7
  coincident P9 A1
  tangent A2 L4
  tangent A1 L3
  tangent A2 L3
  coincident P11 L4
  coincident P7 P12
  dimension "d765" diameter C2 = 13.6
  dimension "d766" diameter C3 = 2.8
  dimension "d767" diameter C1 = 2.8
extrude "Extrude128" new body sketch "Flipper 90" along normal blind 25 bodies "Flipper 90"
sweep "Sweep8" sketch "Rubber Band profile" TwistAngle 0 TaperAngle 0
fillet "Fillet13" radius 2
extrude "Extrude129" add sketch "Flipper 90" profile of C1 L1 L2 C2 C3 against normal blind 31.2
extrude "Extrude130" cut sketch "Flipper 90" profile of L1 L2 C2 blind -20 taper 3 from offset -22.3
extrude "Extrude131" cut sketch "Flipper 90" profile of C1 C3 blind -22 from offset -22
extrude "Extrude132" new body sketch "Flipper 90" profile of C1 L1 L2 C2 C3 against normal blind 32.2 bodies "Flipper 90 + 1"
extrude "Extrude133" add sketch "Flipper 90" along normal blind 25
extrude "Extrude134" cut sketch "Flipper 90" profile of L1 L2 C2 blind -20 taper 3 from offset -23.3
extrude "Extrude135" cut sketch "Flipper 90" profile of C1 C3 blind -20 from offset -20
sweep "Sweep9" sketch "Rubber Band profile" TwistAngle 0 TaperAngle 0
fillet "Fillet14" radius 2
extrude "Extrude136" new body sketch "Flipper 90" along normal blind 25 bodies "Flipper 90 + 2"
extrude "Extrude137" add sketch "Flipper 90" profile of C1 L1 L2 C2 C3 against normal blind 33.2
extrude "Extrude138" cut sketch "Flipper 90" profile of L1 L2 C2 blind -20 taper 3 from offset -24.3
extrude "Extrude139" cut sketch "Flipper 90" profile of C1 C3 blind -20 from offset -24.3
sweep "Sweep10" sketch "Rubber Band profile" TwistAngle 0 TaperAngle 0
fillet "Fillet15" radius 2
extrude "Extrude140" new body sketch "Flipper 90" along normal blind 25 bodies "Flipper 90 + 3"
extrude "Extrude141" add sketch "Flipper 90" profile of C1 L1 L2 C2 C3 against normal blind 34.2
extrude "Extrude142" cut sketch "Flipper 90" profile of L1 L2 C2 blind -20 taper 3 from offset -25.3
